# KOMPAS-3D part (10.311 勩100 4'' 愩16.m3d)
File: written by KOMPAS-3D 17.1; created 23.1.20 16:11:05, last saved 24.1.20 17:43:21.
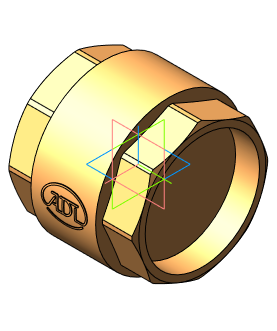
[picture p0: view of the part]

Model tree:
1. Операция без истории:2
